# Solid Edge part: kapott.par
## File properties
Author: Georg
Template: Iso Part.par
Last saved by: Kalle
Revision: 6
Application: Solid Edge
Accuracy: 0,990
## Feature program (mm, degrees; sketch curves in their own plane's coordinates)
sketch for "unnamed Protrusion 1" plane through (0, 0, 0) normal (0, 0, 1) x-axis (1, 0, 0)
  line (0, -13.5) -> (30, -13.5)
  line (30, -13.5) -> (30, 13.5)
  line (30, 13.5) -> (0, 13.5)
  line (0, 13.5) -> (0, -13.5)
  dimension (linear) = 30
extrude "unnamed Protrusion 1" add finite 8 along +normal
sketch for "unnamed Cutout 1" plane through (0, -13.5, 4) normal (0, -1, 0) x-axis (1, 0, 0)
  arc centre (0, -96) radius 100 from (0, 4) to (14.9877, 2.8705) cw
  arc centre (10.4914, -26.7907) radius 30 from (14.9877, 2.8705) to (30, -4) cw
extrude "unnamed Cutout 1" cut to key point along -normal
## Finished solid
Body 1: solid body, 6 faces, 12 edges, 8 vertices.
  Faces by surface: plane 4, cylinder 2
  Edges by curve: line 8, circle 4
Bounding box of the edges (mm): 30.000 x 27.000 x 8.000, from (0, -13.5, 0) to (30, 13.5, 8).
Cylindrical faces by radius (mm): R30 x1, R100 x1
Planar faces by outward normal: +y 1, -x 1, -y 1, -z 1
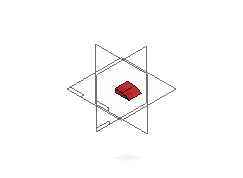
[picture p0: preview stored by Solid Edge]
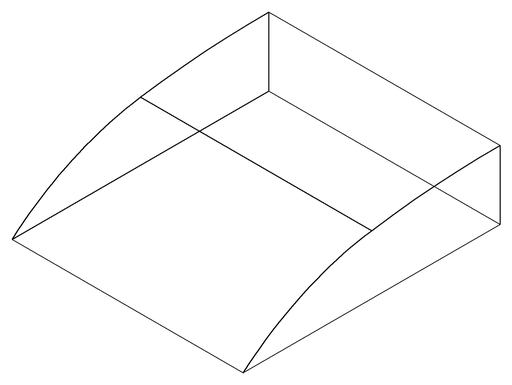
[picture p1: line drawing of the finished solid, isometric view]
